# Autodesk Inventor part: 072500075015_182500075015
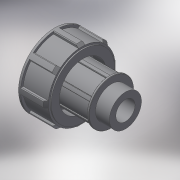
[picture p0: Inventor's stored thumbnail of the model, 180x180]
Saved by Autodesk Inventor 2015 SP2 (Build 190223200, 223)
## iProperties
Created: 2017-04
Part Number: 072500075015_182500075015
Material: Generic
Description: PLASSON THREADED ADAPTOR 75-1.1/2"
Document SubType Name: Modeling
Designer: KIM
Density: 1 g/cm^3
Appearance: Default
Author: KIM
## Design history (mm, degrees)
derived "07250.ipt"
feature "Solid1::07250.ipt"
tag "TaggingFeature1"
body "Solid1"
other parameters: "d1" = 47.803, "d2" = 128, "d3" = 22, "d6" = 132, "d7" = 122.76, "d8" = 105.6, "d9" = 75, "d10" = 81.2651, "d12" = 28.6818, "d13" = 38.2424, "d14" = 25.3, "d15" = 99, "d16" = 3.84, "d17" = 51.2, "d18" = 22, "d19" = 26.4, "d24" = 9.5606, "d25" = 4.7803, "d27" = 0, "d28" = 3.82424, "d31" = 0.95606, "d35" = 360 deg, "d41" = 29.337, "d56" = 78.75, "d57" = 7.5, "d58" = 3.75, "d60" = 0, "d61" = 0.47803, "d64" = 0.47803, "d68" = 360 deg, "d_" = 75, "R_" = 47.803, "E_" = 132, "H_" = 128, "l_2" = 22, "d55" = 75
